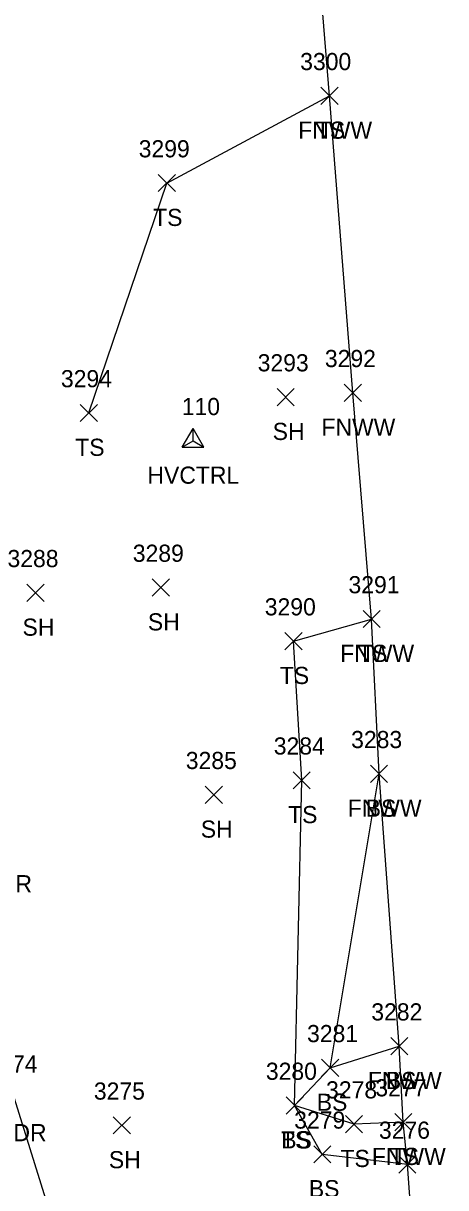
# Model space of a CAD drawing. Extents: x 1650221 to 1650634, y 244606 to 249996.
# Drawn here: x 1650476.7 to 1650525.9, y 245976.3 to 246112 of the extents above; entities that cross this region are included whole.
import ezdxf

# ---------------------------------------------------------------- set-up
doc = ezdxf.new("R2010")
doc.units = 0
for name, color, linetype in [('C_A', 7, 'Continuous'), ('C_I', 7, 'Continuous'), ('CPSM', 7, 'Continuous'), ('L_A', 7, 'Continuous'), ('L_I', 7, 'Continuous'), ('L_TIC', 7, 'Continuous'), ('LAWA', 7, 'Continuous'), ('LELB', 7, 'Continuous'), ('LFNC', 7, 'Continuous'), ('LSOGP', 7, 'Continuous')]:
    doc.layers.add(name, color=color, linetype=linetype)

msp = doc.modelspace()

# ---------------------------------------------------------------- linework, layer by layer
at = {"layer": 'CPSM'}
for p, q in [((1650495.22, 246062.62), (1650496.47, 246064.78)), ((1650497.72, 246062.62), (1650496.47, 246064.78)), ((1650496.47, 246063.34), (1650496.47, 246064.78)), ((1650495.22, 246062.62), (1650496.47, 246063.34)), ((1650495.22, 246062.62), (1650497.72, 246062.62)), ((1650496.47, 246063.34), (1650496.47, 246063.34)), ((1650496.47, 246063.34), (1650497.72, 246062.62))]:
    msp.add_line(p, q, dxfattribs=at)
at = {"layer": 'L_TIC'}
for points in [[(1650511.39, 246102.56), (1650513.39, 246104.56)], [(1650513.39, 246102.56), (1650511.39, 246104.56)], [(1650511.39, 246102.56), (1650513.39, 246104.56)], [(1650513.39, 246102.56), (1650511.39, 246104.56)], [(1650492.41, 246092.39), (1650494.41, 246094.39)], [(1650494.41, 246092.39), (1650492.41, 246094.39)], [(1650506.27, 246067.44), (1650508.27, 246069.44)], [(1650508.27, 246067.44), (1650506.27, 246069.44)], [(1650514.11, 246067.94), (1650516.11, 246069.94)], [(1650516.11, 246067.94), (1650514.11, 246069.94)], [(1650483.33, 246065.59), (1650485.33, 246067.59)], [(1650485.33, 246065.59), (1650483.33, 246067.59)], [(1650477.1, 246044.62), (1650479.1, 246046.62)], [(1650479.1, 246044.62), (1650477.1, 246046.62)], [(1650491.72, 246045.24), (1650493.72, 246047.24)], [(1650493.72, 246045.24), (1650491.72, 246047.24)], [(1650516.3, 246041.57), (1650518.3, 246043.57)], [(1650518.3, 246041.57), (1650516.3, 246043.57)], [(1650516.3, 246041.57), (1650518.3, 246043.57)], [(1650518.3, 246041.57), (1650516.3, 246043.57)], [(1650507.19, 246038.99), (1650509.19, 246040.99)], [(1650509.19, 246038.99), (1650507.19, 246040.99)], [(1650508.15, 246022.77), (1650510.15, 246024.77)], [(1650510.15, 246022.77), (1650508.15, 246024.77)], [(1650517.16, 246023.52), (1650519.16, 246025.52)], [(1650519.16, 246023.52), (1650517.16, 246025.52)], [(1650517.16, 246023.52), (1650519.16, 246025.52)], [(1650519.16, 246023.52), (1650517.16, 246025.52)], [(1650497.89, 246021.08), (1650499.89, 246023.08)], [(1650499.89, 246021.08), (1650497.89, 246023.08)], [(1650519.52, 245991.77), (1650521.52, 245993.77)], [(1650521.52, 245991.77), (1650519.52, 245993.77)], [(1650519.52, 245991.77), (1650521.52, 245993.77)], [(1650521.52, 245991.77), (1650519.52, 245993.77)], [(1650511.46, 245989.24), (1650513.46, 245991.24)], [(1650513.46, 245989.24), (1650511.46, 245991.24)], [(1650511.46, 245989.24), (1650513.46, 245991.24)], [(1650513.46, 245989.24), (1650511.46, 245991.24)], [(1650507.32, 245984.85), (1650509.32, 245986.85)], [(1650509.32, 245984.85), (1650507.32, 245986.85)], [(1650507.32, 245984.85), (1650509.32, 245986.85)], [(1650509.32, 245984.85), (1650507.32, 245986.85)], [(1650487.17, 245982.54), (1650489.17, 245984.54)], [(1650489.17, 245982.54), (1650487.17, 245984.54)], [(1650514.25, 245982.68), (1650516.25, 245984.68)], [(1650516.25, 245982.68), (1650514.25, 245984.68)], [(1650519.99, 245982.92), (1650521.99, 245984.92)], [(1650521.99, 245982.92), (1650519.99, 245984.92)], [(1650519.99, 245982.92), (1650521.99, 245984.92)], [(1650521.99, 245982.92), (1650519.99, 245984.92)], [(1650510.54, 245979.16), (1650512.54, 245981.16)], [(1650512.54, 245979.16), (1650510.54, 245981.16)], [(1650520.47, 245977.98), (1650522.47, 245979.98)], [(1650522.47, 245977.98), (1650520.47, 245979.98)], [(1650520.47, 245977.98), (1650522.47, 245979.98)], [(1650522.47, 245977.98), (1650520.47, 245979.98)]]:
    msp.add_lwpolyline(points, dxfattribs=at)
at = {"layer": 'LAWA'}
msp.add_lwpolyline([(1650483.51, 245961.47), (1650475.64, 245986.69), (1650473.95, 246015.71), (1650471, 246044.2), (1650469.07, 246066.54), (1650472.07, 246095.65), (1650474.9, 246124.52), (1650465.87, 246151.64), (1650463.49, 246169.04), (1650462.42, 246192.61), (1650462.69, 246202.49), (1650464.84, 246226.5), (1650467.45, 246241.25), (1650457.44, 246253.74)], dxfattribs=at)
at = {"layer": 'LELB'}
for points in [[(1650484.33, 246066.59), (1650493.41, 246093.39), (1650512.39, 246103.56)], [(1650520.99, 245983.92), (1650515.25, 245983.68), (1650508.32, 245985.85), (1650509.15, 246023.77), (1650508.19, 246039.99), (1650517.3, 246042.57)], [(1650521.47, 245978.98), (1650511.54, 245980.16), (1650508.32, 245985.85), (1650512.46, 245990.24), (1650518.16, 246024.52)], [(1650512.46, 245990.24), (1650520.52, 245992.77)]]:
    msp.add_lwpolyline(points, dxfattribs=at)
at = {"layer": 'LFNC'}
msp.add_lwpolyline([(1650522.45, 245965.53), (1650521.47, 245978.98), (1650520.99, 245983.92), (1650520.52, 245992.77), (1650518.16, 246024.52), (1650517.3, 246042.57), (1650515.11, 246068.94), (1650512.39, 246103.56), (1650510.38, 246128.44), (1650506.9, 246166.65), (1650504.96, 246207.91), (1650503.06, 246228.04), (1650500.95, 246260.24)], dxfattribs=at)
at = {"layer": 'LSOGP'}
msp.add_lwpolyline([(1650522.45, 245965.53), (1650521.47, 245978.98), (1650520.99, 245983.92), (1650520.52, 245992.77), (1650518.16, 246024.52), (1650517.3, 246042.57), (1650515.11, 246068.94), (1650512.39, 246103.56), (1650510.38, 246128.44), (1650506.9, 246166.65), (1650504.96, 246207.91), (1650503.06, 246228.04), (1650500.95, 246260.24)], dxfattribs=at)

# ---------------------------------------------------------------- texts
at = {"layer": 'C_A'}
msp.add_text('HVCTRL', height=2, dxfattribs=at).set_placement((1650491.16, 246058.34))
at = {"layer": 'C_I'}
msp.add_text('110', height=2, dxfattribs=at).set_placement((1650495.16, 246066.34))
at = {"layer": 'L_A'}
for s, p in [('FNWW', (1650508.74, 246098.56)), ('TS', (1650510.8, 246098.56)), ('TS', (1650491.82, 246088.39)), ('SH', (1650505.76, 246063.44)), ('FNWW', (1650511.45, 246063.94)), ('TS', (1650482.74, 246061.59)), ('SH', (1650476.59, 246040.62)), ('SH', (1650491.21, 246041.24)), ('FNWW', (1650513.64, 246037.57)), ('TS', (1650515.71, 246037.57)), ('TS', (1650506.6, 246034.99)), ('TS', (1650507.56, 246018.77)), ('FNWW', (1650514.51, 246019.52)), ('BS', (1650516.61, 246019.52)), ('SH', (1650497.38, 246017.08)), ('WDR', (1650471.31, 246010.71)), ('FNWW', (1650516.86, 245987.77)), ('BS', (1650518.96, 245987.77)), ('BS', (1650510.9, 245985.24)), ('BS', (1650510.9, 245985.24)), ('WDR', (1650473.01, 245981.69)), ('TS', (1650506.73, 245980.85)), ('BS', (1650506.76, 245980.85)), ('FNWW', (1650517.33, 245978.92)), ('TS', (1650519.4, 245978.92)), ('SH', (1650486.66, 245978.54)), ('TS', (1650513.66, 245978.68)), ('BS', (1650509.98, 245975.16))]:
    msp.add_text(s, height=2, dxfattribs=at).set_placement(p)
at = {"layer": 'L_I'}
for s, p in [('3300', (1650508.97, 246106.56)), ('3300', (1650508.97, 246106.56)), ('3299', (1650490.14, 246096.39)), ('3293', (1650504.01, 246071.44)), ('3292', (1650511.85, 246071.94)), ('3294', (1650481.07, 246069.59)), ('3288', (1650474.84, 246048.62)), ('3289', (1650489.45, 246049.24)), ('3291', (1650514.6, 246045.57)), ('3291', (1650514.6, 246045.57)), ('3290', (1650504.84, 246042.99)), ('3284', (1650505.89, 246026.77)), ('3283', (1650514.91, 246027.52)), ('3283', (1650514.91, 246027.52)), ('3285', (1650495.63, 246025.08)), ('3282', (1650517.26, 245995.77)), ('3282', (1650517.26, 245995.77)), ('3281', (1650509.77, 245993.24)), ('3281', (1650509.77, 245993.24)), ('3274', (1650472.38, 245989.69)), ('3280', (1650504.97, 245988.85)), ('3280', (1650504.97, 245988.85)), ('3275', (1650484.91, 245986.54)), ('3278', (1650511.99, 245986.68)), ('3277', (1650517.73, 245986.92)), ('3277', (1650517.73, 245986.92)), ('3279', (1650508.27, 245983.16)), ('3276', (1650518.15, 245981.98)), ('3276', (1650518.15, 245981.98))]:
    msp.add_text(s, height=2, dxfattribs=at).set_placement(p)

doc.saveas('drawing.dxf')
